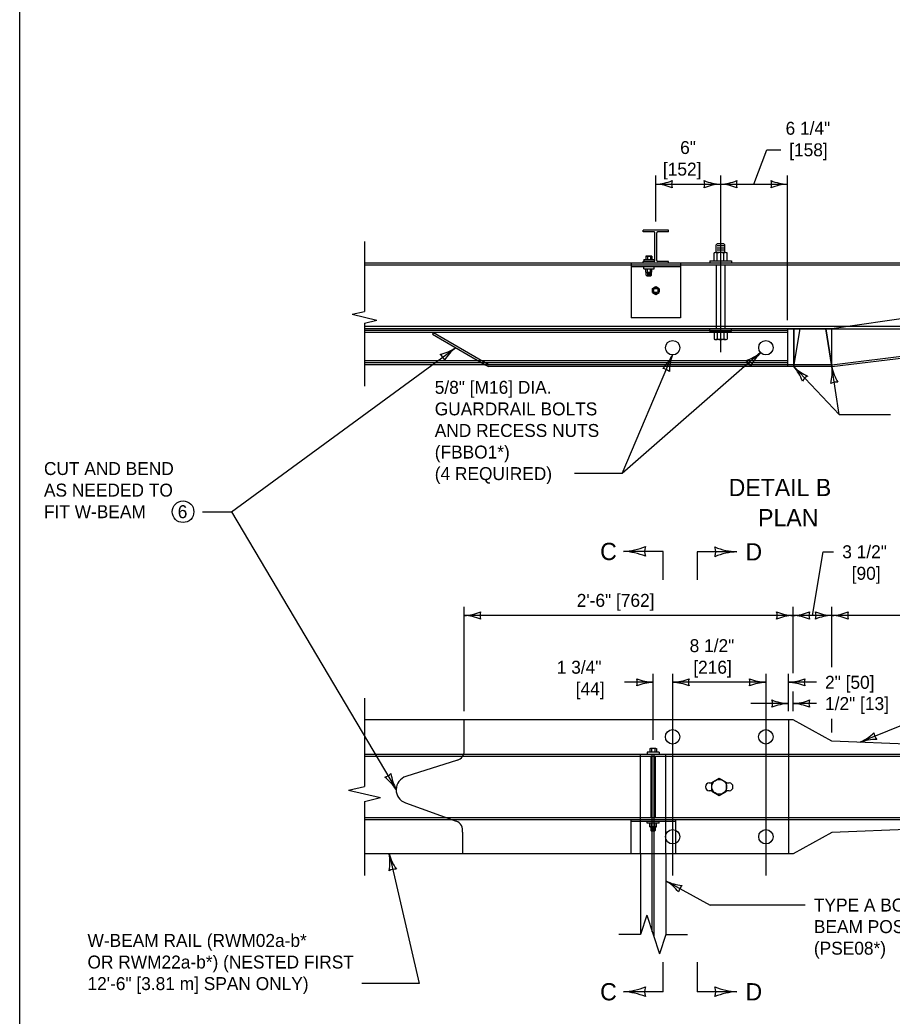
# Model space of a CAD drawing. Extents: x 49991.4 to 50021, y 49987.6 to 50011.4.
# Drawn here: x 49999.384 to 50003.426, y 49990.336 to 49994.953 of the extents above; entities that cross this region are included whole.
import ezdxf

# ---------------------------------------------------------------- set-up
doc = ezdxf.new("R2010")
doc.units = 0
for name, color, linetype in [('Level 1', 7, 'Continuous'), ('Level 2', 7, 'Continuous'), ('Level 3', 7, 'Continuous'), ('Level 4', 7, 'Continuous'), ('Level 5', 7, 'Continuous'), ('Level 6', 7, 'Continuous')]:
    doc.layers.add(name, color=color, linetype=linetype)

msp = doc.modelspace()

# ---------------------------------------------------------------- linework, layer by layer
at = {"layer": 'Level 1'}
for p, q in [((50002.3904, 49993.9782), (50002.272, 49993.9782)), ((50002.272, 49993.9702), (50002.272, 49993.9782)), ((50002.3232, 49993.9702), (50002.272, 49993.9702)), ((50002.3272, 49993.8379), (50002.3272, 49993.9662)), ((50002.3352, 49993.8379), (50002.3352, 49993.9662)), ((50002.3904, 49993.9702), (50002.3392, 49993.9702)), ((50002.3904, 49993.9702), (50002.3904, 49993.9782)), ((50002.6537, 49993.8744), (50002.6088, 49993.8744)), ((50002.6112, 49993.9106), (50002.6162, 49993.9156)), ((50002.6112, 49993.8744), (50002.6112, 49993.9106)), ((50002.6462, 49993.9156), (50002.6162, 49993.9156)), ((50002.6462, 49993.9056), (50002.6162, 49993.9056)), ((50002.6462, 49993.8956), (50002.6162, 49993.8956)), ((50002.6462, 49993.8856), (50002.6162, 49993.8856)), ((50002.6462, 49993.8756), (50002.6162, 49993.8756)), ((50002.6512, 49993.9106), (50002.6462, 49993.9156)), ((50002.6512, 49993.8742), (50002.6512, 49993.9106)), ((50002.272, 49993.8259), (50002.272, 49993.8339)), ((50002.3232, 49993.8339), (50002.272, 49993.8339)), ((50002.2752, 49993.8419), (50002.2752, 49993.8339)), ((50002.2752, 49993.8419), (50002.3232, 49993.8419)), ((50002.2852, 49993.8579), (50002.2852, 49993.8419)), ((50002.2887, 49993.8587), (50002.3097, 49993.8587)), ((50002.2922, 49993.8579), (50002.2922, 49993.8419)), ((50002.3063, 49993.8579), (50002.3063, 49993.8419)), ((50002.3132, 49993.8579), (50002.3132, 49993.8419)), ((50002.3232, 49993.8419), (50002.3232, 49993.8339)), ((50002.3904, 49993.8339), (50002.3392, 49993.8339)), ((50002.3904, 49993.8259), (50002.3904, 49993.8339)), ((50002.5811, 49993.8358), (50002.5811, 49993.8259)), ((50002.5811, 49993.8358), (50002.6813, 49993.8358)), ((50002.6012, 49993.8371), (50002.6012, 49993.8731)), ((50002.6162, 49993.837), (50002.6162, 49993.8732)), ((50002.6462, 49993.837), (50002.6462, 49993.8732)), ((50002.6612, 49993.8371), (50002.6612, 49993.8731)), ((50002.6813, 49993.8358), (50002.6813, 49993.8259)), ((50005.2826, 49993.8259), (50000.9808, 49993.8259)), ((50002.6813, 49993.8259), (50002.5811, 49993.8259)), ((50002.3152, 49993.7081), (50002.3312, 49993.7173)), ((50002.3152, 49993.6897), (50002.3152, 49993.7081)), ((50002.3152, 49993.6897), (50002.3312, 49993.6804)), ((50002.3312, 49993.7173), (50002.3472, 49993.7081)), ((50002.3312, 49993.6804), (50002.3472, 49993.6897)), ((50002.3472, 49993.6897), (50002.3472, 49993.7081)), ((50004.5422, 49993.7204), (50003.1472, 49993.5219)), ((50003.1472, 49993.5219), (50000.9808, 49993.5219)), ((50002.9704, 49993.3459), (50002.9704, 49993.5219)), ((50002.9704, 49993.3459), (50003.0004, 49993.5219)), ((50003.1472, 49993.3459), (50003.1196, 49993.5219)), ((50003.1472, 49993.3459), (50004.5672, 49993.5219)), ((50003.1472, 49993.3459), (50003.1472, 49993.5219)), ((50001.5399, 49993.355), (50000.9808, 49993.355)), ((50001.5399, 49993.355), (50001.5556, 49993.3459)), ((50003.1472, 49993.3459), (50001.5556, 49993.3459)), ((50002.9672, 49991.7096), (50000.9808, 49991.7096)), ((50001.4432, 49991.5639), (50001.4432, 49991.7096)), ((50003.1472, 49991.6104), (50002.9672, 49991.7096)), ((50004.5668, 49991.5504), (50003.1472, 49991.6104)), ((50001.412, 49991.5222), (50001.1728, 49991.4464)), ((50001.1704, 49991.324), (50001.4062, 49991.2388)), ((50004.5668, 49991.2464), (50003.1472, 49991.1864)), ((50001.4349, 49991.1883), (50001.4349, 49991.0872)), ((50003.1472, 49991.1864), (50002.9672, 49991.0872)), ((50002.9672, 49991.0872), (50000.9808, 49991.0872)), ((50002.2599, 49991.0872), (50002.2599, 49990.7137)), ((50002.3779, 49991.0872), (50002.3779, 49990.7137))]:
    msp.add_line(p, q, dxfattribs=at)
msp.add_lwpolyline([(49999.3835, 49998.9992), (50016.7501, 49998.9992), (50016.7501, 49987.7988), (49999.3835, 49987.7988)], close=True, dxfattribs=at)
for points in [[(50003.0004, 49993.5219), (50002.9704, 49993.5219), (50002.9704, 49993.3459), (50003.0004, 49993.5219)], [(50003.1472, 49993.5219), (50003.1196, 49993.5219), (50003.1472, 49993.3459), (50003.1472, 49993.5219)]]:
    msp.add_lwpolyline(points, dxfattribs=at)
for centre, radius in [((50002.3312, 49993.6989), 0.016), ((50002.3312, 49993.6989), 0.01), ((50002.4092, 49993.4336), 0.0333), ((50002.8414, 49993.4336), 0.0333), ((50002.409, 49991.63), 0.0333), ((50002.8412, 49991.63), 0.0333), ((50002.4092, 49991.1669), 0.0333), ((50002.8415, 49991.1669), 0.0333)]:
    msp.add_circle(centre, radius, dxfattribs=at)
for centre, radius, start, end in [((50002.3232, 49993.9662), 0.004, 0, 90), ((50002.3392, 49993.9662), 0.004, 90, 180), ((50002.3232, 49993.8379), 0.004, 270, 0), ((50002.3392, 49993.8379), 0.004, 180, 270), ((50001.3985, 49991.5649), 0.0447, 287.5704, 358.7363), ((50001.1923, 49991.3848), 0.0646, 107.5889, 250.1803), ((50001.391, 49991.1967), 0.0447, 349.2089, 70.1356)]:
    msp.add_arc(centre, radius, start, end, dxfattribs=at)
for centre, major_axis, ratio, start_param, end_param in [((50002.6087, 49993.865), (-0.015, 0), 0.623816, 4.198439, 5.235988), ((50002.6312, 49993.8369), (-0.06, 0), 0.623816, 4.457545, 4.967234), ((50002.6537, 49993.865), (-0.015, 0), 0.623816, 4.188789, 5.226338), ((50002.2887, 49993.8522), (0.007, 0), 0.93686, 1.056847, 2.094396), ((50002.2992, 49993.8325), (0.028, 0), 0.93686, 1.315951, 1.825641), ((50002.3097, 49993.8522), (0.007, 0), 0.93686, 1.047198, 2.084746), ((50002.6087, 49993.8452), (-0.015, 0), 0.623816, 1.047198, 2.084746), ((50002.6312, 49993.8732), (-0.06, 0), 0.623816, 1.31595, 1.825641), ((50002.6537, 49993.8452), (-0.015, 0), 0.623816, 1.056847, 2.094396)]:
    msp.add_ellipse(centre, major_axis=major_axis, ratio=ratio, start_param=start_param, end_param=end_param, dxfattribs=at)
at = {"layer": 'Level 2'}
msp.add_circle((50000.1395, 49992.6736), 0.0503, dxfattribs=at)
at = {"layer": 'Level 3'}
for p, q in [((50002.3312, 49994.0182), (50002.3312, 49994.2316)), ((50002.9412, 49993.5619), (50002.9412, 49994.2316)), ((50002.3312, 49994.1916), (50002.6313, 49994.1916)), ((50002.6313, 49994.1916), (50002.9412, 49994.1916)), ((50000.3638, 49992.6736), (50001.4032, 49993.4339)), ((50002.8171, 49993.4108), (50002.1755, 49992.8501)), ((50002.1755, 49992.8501), (50002.4085, 49993.4003)), ((50002.9704, 49993.3459), (50003.1817, 49993.1247)), ((50003.1817, 49993.1247), (50003.1472, 49993.3459)), ((50003.1817, 49993.1247), (50003.4191, 49993.1247)), ((50002.1755, 49992.8501), (50001.955, 49992.8501)), ((50000.2298, 49992.6736), (50000.3638, 49992.6736)), ((50000.3638, 49992.6736), (50001.1277, 49991.3861)), ((50003.0572, 49992.1926), (50003.1064, 49992.488)), ((50003.1064, 49992.488), (50003.1555, 49992.488)), ((50001.4432, 49991.7496), (50001.4432, 49992.2326)), ((50002.9672, 49991.9246), (50002.9672, 49992.2326)), ((50003.1472, 49991.9528), (50003.1472, 49992.2326)), ((50002.9672, 49992.1926), (50001.4432, 49992.1926)), ((50003.1472, 49992.1926), (50002.9672, 49992.1926)), ((50004.5668, 49992.1926), (50003.1472, 49992.1926)), ((50002.3189, 49991.6162), (50002.3189, 49991.9227)), ((50002.9457, 49991.7496), (50002.9457, 49991.9227)), ((50002.3189, 49991.8827), (50002.1864, 49991.8827)), ((50002.841, 49991.8827), (50002.409, 49991.8827)), ((50003.0756, 49991.8827), (50002.9457, 49991.8827)), ((50002.9672, 49991.7496), (50002.9672, 49991.8406)), ((50002.9457, 49991.7841), (50002.7723, 49991.7841)), ((50003.0756, 49991.7841), (50002.9672, 49991.7841)), ((50003.1472, 49991.6504), (50003.1472, 49991.7142)), ((50003.6208, 49991.7439), (50003.2784, 49991.6048)), ((50001.0948, 49991.0872), (50001.2342, 49990.4862)), ((50002.3779, 49990.9621), (50002.5834, 49990.8503)), ((50003.0239, 49990.8503), (50002.5834, 49990.8503)), ((50001.2342, 49990.4862), (50000.9683, 49990.4862))]:
    msp.add_line(p, q, dxfattribs=at)
msp.add_lwpolyline([(50002.7862, 49994.1916), (50002.8454, 49994.351), (50002.91, 49994.351)], dxfattribs=at)
for centre, radius, start, end in [((50002.3221, 49994.4138), 0.2223, 272.3605, 292.544), ((50002.4594, 49994.1916), 0.0548, 162.1388, 197.8612), ((50002.503, 49994.1916), 0.0548, 342.1388, 17.8612), ((50002.6427, 49994.4243), 0.233, 247.9228, 267.1727), ((50002.6221, 49994.4138), 0.2223, 272.3605, 292.544), ((50002.7595, 49994.1916), 0.0548, 162.1388, 197.8612), ((50002.813, 49994.1916), 0.0548, 342.1388, 17.8612), ((50002.9527, 49994.4243), 0.233, 247.9228, 267.1727), ((50002.3197, 49993.9589), 0.233, 67.9228, 87.1727), ((50002.6404, 49993.9695), 0.2223, 92.3605, 112.544), ((50002.6198, 49993.9589), 0.233, 67.9228, 87.1727), ((50002.9504, 49993.9695), 0.2223, 92.3605, 112.544), ((50001.2751, 49993.6285), 0.233, 284.1057, 303.3556), ((50001.5417, 49993.26), 0.2223, 128.5434, 148.7269), ((50001.2997, 49993.3582), 0.0548, 18.3217, 54.0441), ((50002.1987, 49993.5017), 0.233, 314.9695, 334.2194), ((50002.6166, 49993.3221), 0.2223, 159.4072, 179.5907), ((50002.6726, 49993.5936), 0.233, 289.0724, 308.3222), ((50002.7205, 49993.3265), 0.0548, 23.2884, 59.0107), ((50002.9702, 49993.2496), 0.2223, 133.51, 153.6935), ((50002.3585, 49993.2823), 0.0548, 49.1855, 84.9079), ((50003.1246, 49993.506), 0.2223, 226.0648, 246.2483), ((50002.7942, 49993.1934), 0.233, 21.6272, 40.877), ((50002.9155, 49993.3213), 0.233, 346.795, 6.0448), ((50003.3653, 49993.3892), 0.2223, 191.2326, 211.4161), ((50003.059, 49993.2532), 0.0548, 115.8432, 151.5655), ((50003.167, 49993.2192), 0.0548, 81.0109, 116.7333), ((50001.4341, 49992.4147), 0.2223, 272.3605, 292.544), ((50001.4317, 49991.9599), 0.233, 67.9228, 87.1727), ((50001.5714, 49992.1926), 0.0548, 162.1388, 197.8612), ((50002.9764, 49992.4147), 0.2223, 247.456, 267.6395), ((50002.839, 49992.1926), 0.0548, 342.1388, 17.8612), ((50002.9787, 49991.9599), 0.233, 92.8273, 112.0772), ((50002.9581, 49992.4147), 0.2223, 272.3605, 292.544), ((50002.9557, 49991.9599), 0.233, 67.9228, 87.1727), ((50003.0954, 49992.1926), 0.0548, 162.1388, 197.8612), ((50003.019, 49992.1926), 0.0548, 342.1388, 17.8612), ((50003.1587, 49992.4253), 0.233, 247.9228, 267.1727), ((50003.1564, 49991.9705), 0.2223, 92.3605, 112.544), ((50003.1381, 49992.4147), 0.2223, 272.3605, 292.544), ((50003.1357, 49991.9599), 0.233, 67.9228, 87.1727), ((50003.2754, 49992.1926), 0.0548, 162.1388, 197.8612), ((50002.1906, 49991.8827), 0.0548, 342.1388, 17.8612), ((50002.3303, 49992.1154), 0.233, 247.9228, 267.1727), ((50002.3999, 49992.1048), 0.2223, 272.3605, 292.544), ((50002.5372, 49991.8827), 0.0548, 162.1388, 197.8612), ((50002.7128, 49991.8827), 0.0548, 342.1388, 17.8612), ((50002.8525, 49992.1154), 0.233, 247.9228, 267.1727), ((50002.9365, 49992.1048), 0.2223, 272.3605, 292.544), ((50003.0739, 49991.8827), 0.0548, 162.1388, 197.8612), ((50002.328, 49991.6606), 0.2223, 92.3605, 112.544), ((50002.3975, 49991.65), 0.233, 67.9228, 87.1727), ((50002.8502, 49991.6606), 0.2223, 92.3605, 112.544), ((50002.9342, 49991.65), 0.233, 67.9228, 87.1727), ((50002.8175, 49991.7841), 0.0548, 342.1388, 17.8612), ((50002.9572, 49992.0168), 0.233, 247.9228, 267.1727), ((50002.9581, 49992.0062), 0.2223, 272.3605, 292.544), ((50003.0954, 49991.7841), 0.0548, 162.1388, 197.8612), ((50002.9549, 49991.562), 0.2223, 92.3605, 112.544), ((50002.9557, 49991.5514), 0.233, 67.9228, 87.1727), ((50003.1801, 49991.8161), 0.233, 294.9424, 314.1922), ((50003.3535, 49991.3956), 0.2223, 89.5711, 109.7546), ((50003.3972, 49991.6531), 0.0548, 184.2539, 219.9762), ((50001.0623, 49991.4963), 0.0548, 282.8181, 318.5404), ((50000.9413, 49991.2648), 0.2223, 33.0397, 53.2232), ((50001.3337, 49991.4949), 0.233, 188.6021, 207.8519), ((50001.3091, 49991.1463), 0.2223, 195.4234, 215.6069), ((50000.8655, 49991.0458), 0.233, 350.9857, 10.2356), ((50001.1237, 49990.9623), 0.0548, 85.2017, 120.9241), ((50002.4759, 49991.1616), 0.2223, 243.8374, 264.0209), ((50002.2566, 49990.7631), 0.233, 39.3997, 58.6496), ((50002.4905, 49990.9008), 0.0548, 133.6157, 169.3381)]:
    msp.add_arc(centre, radius, start, end, dxfattribs=at)
at = {"layer": 'Level 4'}
for p, q in [((50005.2826, 49993.8163), (50000.9808, 49993.8163)), ((50002.2162, 49993.8259), (50002.2162, 49993.5719)), ((50002.4462, 49993.8079), (50002.2162, 49993.8079)), ((50002.2752, 49993.7999), (50002.2752, 49993.8079)), ((50002.2752, 49993.7999), (50002.3232, 49993.7999)), ((50002.2852, 49993.7839), (50002.2852, 49993.7999)), ((50002.2872, 49993.7699), (50002.2872, 49993.7831)), ((50002.2887, 49993.783), (50002.3097, 49993.783)), ((50002.3072, 49993.782), (50002.2912, 49993.782)), ((50002.2922, 49993.7838), (50002.2922, 49993.7999)), ((50002.3063, 49993.7838), (50002.3063, 49993.7999)), ((50002.3112, 49993.7699), (50002.3112, 49993.7831)), ((50002.3132, 49993.7839), (50002.3132, 49993.7999)), ((50002.3232, 49993.7999), (50002.3232, 49993.8079)), ((50002.4462, 49993.8259), (50002.4462, 49993.5719)), ((50002.6112, 49993.8163), (50002.6112, 49993.5219)), ((50002.6512, 49993.8163), (50002.6512, 49993.5219)), ((50002.2912, 49993.7659), (50002.2872, 49993.7699)), ((50002.3072, 49993.7785), (50002.2912, 49993.7785)), ((50002.3072, 49993.775), (50002.2912, 49993.775)), ((50002.3072, 49993.7714), (50002.2912, 49993.7714)), ((50002.3072, 49993.7659), (50002.2912, 49993.7659)), ((50002.3072, 49993.7659), (50002.3112, 49993.7699)), ((50002.4462, 49993.5719), (50002.2162, 49993.5719)), ((50005.2826, 49993.5315), (50000.9808, 49993.5315)), ((50002.9412, 49993.5128), (50000.9808, 49993.5128)), ((50002.5811, 49993.5099), (50002.5811, 49993.5219)), ((50002.5811, 49993.5099), (50002.6813, 49993.5099)), ((50002.6012, 49993.5087), (50002.6012, 49993.4726)), ((50002.6162, 49993.5087), (50002.6162, 49993.4726)), ((50002.6462, 49993.5087), (50002.6462, 49993.4726)), ((50002.6612, 49993.5087), (50002.6612, 49993.4726)), ((50002.6813, 49993.5099), (50002.6813, 49993.5219)), ((50002.9412, 49993.5219), (50002.9412, 49993.3459)), ((50002.9414, 49993.5219), (50004.5672, 49993.5219)), ((50003.1467, 49993.355), (50004.5661, 49993.5309)), ((50002.9412, 49993.5037), (50000.9808, 49993.5037)), ((50001.3005, 49993.5037), (50001.296, 49993.4958)), ((50001.296, 49993.4958), (50001.5399, 49993.355)), ((50001.3005, 49993.5037), (50001.5581, 49993.355)), ((50002.6537, 49993.4714), (50002.6088, 49993.4714)), ((50002.9412, 49993.3732), (50000.9808, 49993.3732)), ((50002.9412, 49993.3641), (50000.9808, 49993.3641)), ((50003.1467, 49993.355), (50001.5399, 49993.355)), ((50002.9457, 49991.7096), (50002.9457, 49991.0872)), ((50002.3028, 49991.5752), (50002.3028, 49991.5584)), ((50002.3308, 49991.5762), (50002.3069, 49991.5762)), ((50002.3108, 49991.5752), (50002.3108, 49991.5584)), ((50002.3269, 49991.5752), (50002.3269, 49991.5584)), ((50002.3348, 49991.5752), (50002.3348, 49991.5584)), ((50000.9808, 49991.5504), (50004.5668, 49991.5504)), ((50000.9808, 49991.5408), (50005.2826, 49991.5408)), ((50002.2599, 49991.0872), (50002.2599, 49991.5504)), ((50002.2908, 49991.5584), (50002.2908, 49991.5504)), ((50002.3468, 49991.5584), (50002.2908, 49991.5584)), ((50002.3088, 49991.5408), (50002.3088, 49991.256)), ((50002.3149, 49990.7258), (50002.3149, 49991.5504)), ((50002.3229, 49990.7016), (50002.3229, 49991.5504)), ((50002.3288, 49991.5408), (50002.3288, 49991.256)), ((50002.3468, 49991.5584), (50002.3468, 49991.5504)), ((50002.3779, 49991.0872), (50002.3779, 49991.5504)), ((50002.5909, 49991.4181), (50002.6252, 49991.438)), ((50002.6252, 49991.438), (50002.6596, 49991.4181)), ((50002.5791, 49991.4174), (50002.5909, 49991.4174)), ((50002.5909, 49991.3785), (50002.5909, 49991.4181)), ((50002.6596, 49991.3785), (50002.6596, 49991.4181)), ((50002.6596, 49991.4174), (50002.6716, 49991.4174)), ((50002.5909, 49991.3792), (50002.5791, 49991.3792)), ((50002.5909, 49991.3785), (50002.6252, 49991.3587)), ((50002.6252, 49991.3587), (50002.6596, 49991.3785)), ((50002.6716, 49991.3792), (50002.6596, 49991.3792)), ((50000.9808, 49991.256), (50005.2826, 49991.256)), ((50000.9808, 49991.2464), (50004.5668, 49991.2464)), ((50002.2158, 49991.2464), (50002.2158, 49991.0872)), ((50002.4219, 49991.2464), (50002.4219, 49991.0872)), ((50002.2158, 49991.2384), (50002.4219, 49991.2384)), ((50002.2908, 49991.2304), (50002.2908, 49991.2384)), ((50002.3468, 49991.2304), (50002.2908, 49991.2304)), ((50002.3028, 49991.2136), (50002.3028, 49991.2304)), ((50002.3308, 49991.2126), (50002.3069, 49991.2126)), ((50002.3088, 49991.2126), (50002.3088, 49991.1954)), ((50002.3108, 49991.2135), (50002.3108, 49991.2304)), ((50002.3268, 49991.2104), (50002.3108, 49991.2104)), ((50002.3268, 49991.2074), (50002.3108, 49991.2074)), ((50002.3268, 49991.2044), (50002.3108, 49991.2044)), ((50002.3268, 49991.2014), (50002.3108, 49991.2014)), ((50002.3268, 49991.1984), (50002.3108, 49991.1984)), ((50002.3269, 49991.2135), (50002.3269, 49991.2304)), ((50002.3288, 49991.2126), (50002.3288, 49991.1954)), ((50002.3348, 49991.2136), (50002.3348, 49991.2304)), ((50002.3468, 49991.2304), (50002.3468, 49991.2384)), ((50002.3108, 49991.1934), (50002.3088, 49991.1954)), ((50002.3268, 49991.1954), (50002.3108, 49991.1954)), ((50002.3268, 49991.1934), (50002.3108, 49991.1934)), ((50002.3288, 49991.1954), (50002.3268, 49991.1934))]:
    msp.add_line(p, q, dxfattribs=at)
msp.add_circle((50002.6252, 49991.3983), 0.0344, dxfattribs=at)
for centre, start, end in [((50002.581, 49991.3983), 95.8503, 264.1497), ((50002.6696, 49991.3983), 275.8503, 84.1497)]:
    msp.add_arc(centre, 0.0192, start, end, dxfattribs=at)
for centre, major_axis, ratio, start_param, end_param in [((50002.2887, 49993.7895), (0.007, 0), 0.93686, 4.188789, 5.226338), ((50002.2992, 49993.8092), (0.028, 0), 0.93686, 4.457545, 4.967234), ((50002.3097, 49993.7895), (0.007, 0), 0.93686, 4.198439, 5.235988), ((50002.6087, 49993.5005), (-0.015, 0), 0.623816, 4.198439, 5.235988), ((50002.6312, 49993.4725), (-0.06, 0), 0.623816, 4.457545, 4.967235), ((50002.6537, 49993.5005), (-0.015, 0), 0.623816, 4.188789, 5.226338), ((50002.6087, 49993.4807), (-0.015, 0), 0.623816, 1.047198, 2.084746), ((50002.6312, 49993.5088), (-0.06, 0), 0.623816, 1.315951, 1.825641), ((50002.6537, 49993.4807), (-0.015, 0), 0.623816, 1.056847, 2.094396), ((50002.3068, 49991.5687), (-0.008, 0), 0.93686, 4.198439, 5.235988), ((50002.3188, 49991.5462), (-0.032, 0), 0.93686, 4.457545, 4.967234), ((50002.3308, 49991.5687), (-0.008, 0), 0.93686, 4.188789, 5.226338), ((50002.3068, 49991.22), (-0.008, 0), 0.93686, 1.047198, 2.084746), ((50002.3188, 49991.2425), (-0.032, 0), 0.93686, 1.315951, 1.825641), ((50002.3308, 49991.22), (-0.008, 0), 0.93686, 1.056847, 2.094396)]:
    msp.add_ellipse(centre, major_axis=major_axis, ratio=ratio, start_param=start_param, end_param=end_param, dxfattribs=at)
at = {"layer": 'Level 5'}
for p, q in [((50002.6313, 49994.2316), (50002.6313, 49993.4132)), ((50002.409, 49991.9227), (50002.409, 49990.9872)), ((50002.841, 49991.9227), (50002.841, 49990.9872))]:
    msp.add_line(p, q, dxfattribs=at)
at = {"layer": 'Level 6'}
for p, q in [((50000.9808, 49993.9259), (50000.9808, 49993.6019)), ((50000.9241, 49993.5887), (50000.9808, 49993.6019)), ((50000.9241, 49993.5887), (50000.9808, 49993.5751)), ((50000.9808, 49993.5751), (50001.0378, 49993.5617)), ((50000.9808, 49993.5481), (50001.0378, 49993.5617)), ((50000.9808, 49993.5481), (50000.9808, 49993.255)), ((50002.3645, 49992.4894), (50002.1812, 49992.4894)), ((50002.3645, 49992.3584), (50002.3645, 49992.4894)), ((50002.7067, 49992.4876), (50002.5234, 49992.4876)), ((50002.5234, 49992.4876), (50002.5234, 49992.3584)), ((50000.9808, 49991.8096), (50000.9808, 49991.4005)), ((50000.9071, 49991.3834), (50000.9808, 49991.4005)), ((50000.9071, 49991.3834), (50000.9808, 49991.3657)), ((50000.9808, 49991.3657), (50001.0549, 49991.3483)), ((50000.9808, 49991.3306), (50001.0549, 49991.3483)), ((50000.9808, 49991.3306), (50000.9808, 49990.9872)), ((50002.2894, 49990.8033), (50002.2599, 49990.7137)), ((50002.2894, 49990.8033), (50002.3189, 49990.7137)), ((50002.2599, 49990.7137), (50002.1599, 49990.7137)), ((50002.3189, 49990.7137), (50002.3484, 49990.6241)), ((50002.3779, 49990.7137), (50002.3484, 49990.6241)), ((50002.3779, 49990.7137), (50002.4779, 49990.7137)), ((50002.3645, 49990.4483), (50002.3645, 49990.5863)), ((50002.5234, 49990.5863), (50002.5234, 49990.4483)), ((50002.3645, 49990.4483), (50002.1812, 49990.4483)), ((50002.7067, 49990.4483), (50002.5234, 49990.4483))]:
    msp.add_line(p, q, dxfattribs=at)
for centre, radius, start, end in [((50002.169, 49992.7856), 0.2964, 272.3605, 292.544), ((50002.1659, 49992.1791), 0.3107, 67.9228, 87.1727), ((50002.3521, 49992.4894), 0.073, 162.1388, 197.8612), ((50002.5357, 49992.4876), 0.073, 342.1388, 17.8612), ((50002.722, 49992.7979), 0.3107, 247.9228, 267.1727), ((50002.7189, 49992.1914), 0.2964, 92.3605, 112.544), ((50002.169, 49990.7445), 0.2964, 272.3605, 292.544), ((50002.3521, 49990.4483), 0.073, 162.1388, 197.8612), ((50002.5357, 49990.4483), 0.073, 342.1388, 17.8612), ((50002.722, 49990.7586), 0.3107, 247.9228, 267.1727), ((50002.1659, 49990.138), 0.3107, 67.9228, 87.1727), ((50002.7189, 49990.1521), 0.2964, 92.3605, 112.544)]:
    msp.add_arc(centre, radius, start, end, dxfattribs=at)

# ---------------------------------------------------------------- texts
at = {"layer": 'Level 2'}
for s, height, p in [('6 1/4"', 0.06, (50002.9327, 49994.421)), ('6"', 0.06, (50002.444, 49994.3316)), ('[158]', 0.06, (50002.9496, 49994.321)), ('[152]', 0.06, (50002.3641, 49994.2316)), ('CUT AND BEND', 0.06, (49999.4949, 49992.8436)), ('DETAIL B', 0.08, (50002.6687, 49992.7459)), ('AS NEEDED TO', 0.06, (49999.4949, 49992.7436)), ('FIT W-BEAM', 0.06, (49999.4949, 49992.6436)), ('6', 0.06, (50000.115, 49992.6436)), ('PLAN', 0.08, (50002.8053, 49992.6059)), ('C', 0.08, (50002.0731, 49992.4494)), ('D', 0.08, (50002.7467, 49992.4476)), ('2\'-6" [762]', 0.06, (50001.9646, 49992.2326)), ('8 1/2"', 0.06, (50002.488, 49992.0227)), ('1 3/4"', 0.06, (50001.8722, 49991.9227)), ('[216]', 0.06, (50002.5048, 49991.9227)), ('2" [50]', 0.06, (50003.1156, 49991.8528)), ('[44]', 0.06, (50001.9598, 49991.8227)), ('1/2" [13]', 0.06, (50003.1156, 49991.7542)), ('TYPE A BOX', 0.06, (50003.0639, 49990.8203)), ('BEAM POST', 0.06, (50003.0639, 49990.7203)), ('(PSE08*)', 0.06, (50003.0639, 49990.6203)), ('C', 0.08, (50002.0731, 49990.4084)), ('D', 0.08, (50002.7467, 49990.4083))]:
    msp.add_text(s, height=height, dxfattribs=at).set_placement(p)
for s, p in [('5/8" [M16] DIA. ', (50001.3064, 49993.2201)), ('GUARDRAIL BOLTS ', (50001.3064, 49993.1201)), ('AND RECESS NUTS ', (50001.3064, 49993.0201)), ('(FBBO1*)', (50001.3064, 49992.9201)), ('(4 REQUIRED)', (50001.3064, 49992.8201)), ('3 1/2"', (50003.1955, 49992.458)), ('[90]', (50003.2393, 49992.358)), ('W-BEAM RAIL (RWM02a-b* ', (49999.6968, 49990.6562)), ('OR RWM22a-b*) (NESTED FIRST', (49999.6968, 49990.5562)), ('12\'-6" [3.81 m] SPAN ONLY)', (49999.6968, 49990.4562))]:
    msp.add_text(s, height=0.06, rotation=360, dxfattribs=at).set_placement(p)

doc.saveas('drawing.dxf')
